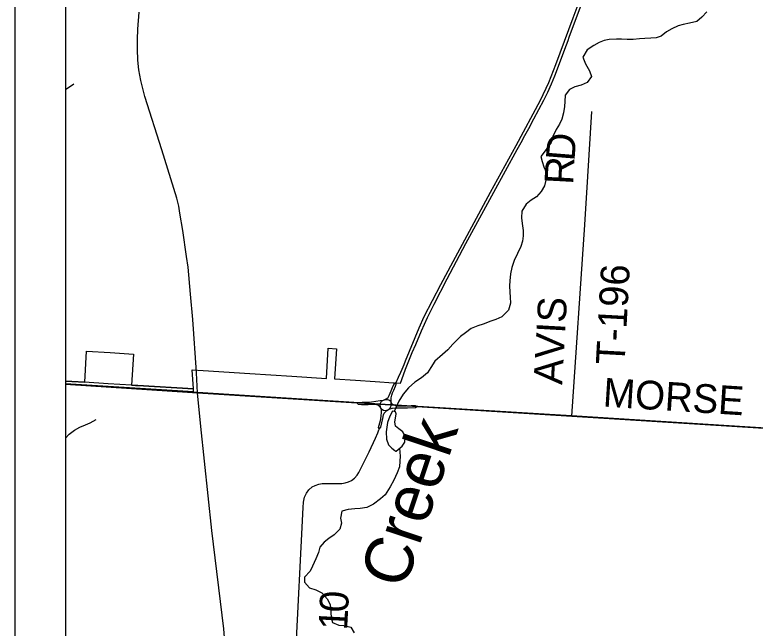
# Model space of a CAD drawing. Extents: x 0 to 91.3, y -0.7 to 22.
# Drawn here: x 2 to 3.464, y 15.231 to 16.443 of the extents above; entities that cross this region are included whole.
import ezdxf

# ---------------------------------------------------------------- set-up
doc = ezdxf.new("R2010")
doc.units = 0
for name, color, linetype in [('GM_X_City_Street', 7, 'Continuous'), ('GM_X_Corporation', 7, 'Continuous'), ('GM_X_County_Road', 7, 'Continuous'), ('GM_X_County_Road_Text', 7, 'Continuous'), ('GM_X_Minor_Lake', 7, 'Continuous'), ('GM_X_Minor_River', 7, 'Continuous'), ('GM_X_Minor_River_Text', 7, 'Continuous'), ('GM_X_Township_Road', 7, 'Continuous'), ('GM_X_Township_Road_Text', 7, 'Continuous'), ('SH_Data', 7, 'Continuous')]:
    doc.layers.add(name, color=color, linetype=linetype)

msp = doc.modelspace()

# ---------------------------------------------------------------- linework, layer by layer
at = {"layer": 'GM_X_City_Street'}
msp.add_line((2.1164, 16.3065), (2.1, 16.2954), dxfattribs=at)
at = {"layer": 'GM_X_Corporation'}
for points in [[(2.1, 20.8844), (2.1, 14.1), (4.5273, 14.1), (4.5361, 14.2234), (4.5616, 14.5843), (4.5901, 15.0403), (4.6027, 15.2253), (4.6241, 15.5494), (4.624, 15.5538), (4.6966, 16.7952), (4.7039, 16.921), (4.7369, 17.4842), (4.7381, 17.5094), (4.7391, 17.5254), (4.7562, 17.8002), (4.7688, 17.9561), (4.7799, 18.0944), (4.7833, 18.1361), (4.8242, 18.6326)], [(2.1, 20.8844), (2.1, 15.7138), (2.3611, 15.6969), (2.7426, 15.6727), (3.1007, 15.6507), (3.7652, 15.6088), (4.1118, 15.5861), (4.6241, 15.5494), (4.624, 15.5538), (4.6966, 16.7952), (4.7039, 16.921), (4.7369, 17.4842), (4.7381, 17.5094), (4.7391, 17.5254), (4.7562, 17.8002), (4.7688, 17.9561), (4.7799, 18.0944), (4.7833, 18.1361), (4.8242, 18.6326)], [(2.1, 19.7378), (2.1, 15.7194), (2.1381, 15.7171), (2.1418, 15.7788), (2.1882, 15.7758), (2.2344, 15.7729), (2.2307, 15.7114), (2.2386, 15.7109), (2.2429, 15.7106), (2.3529, 15.7042), (2.3503, 15.7415), (2.3722, 15.7401), (2.4649, 15.7342), (2.5474, 15.729), (2.6159, 15.7246), (2.6196, 15.7843), (2.6356, 15.7834), (2.6317, 15.7236), (2.6736, 15.721), (2.7121, 15.7185), (2.7484, 15.7162), (2.7508, 15.7161), (2.7626, 15.7153), (2.7651, 15.7226), (2.772, 15.7427), (2.7787, 15.7592), (2.7857, 15.7757), (2.7929, 15.792), (2.8036, 15.819), (2.8156, 15.8454), (2.8288, 15.8713), (2.8547, 15.9217), (2.8915, 15.9917), (2.9467, 16.093), (2.9928, 16.1772), (3.0007, 16.191), (3.0085, 16.2049), (3.0162, 16.219), (3.0262, 16.2376), (3.0361, 16.2562), (3.046, 16.2749), (3.0536, 16.2907), (3.0608, 16.3068), (3.0675, 16.3231), (3.0905, 16.3839), (3.0938, 16.3928), (3.0961, 16.399), (3.1204, 16.4646)]]:
    msp.add_lwpolyline(points, dxfattribs=at)
for points in [[(2.1, 15.7194), (2.1, 15.7146), (2.3533, 15.6987), (2.3529, 15.7044), (2.2429, 15.7106), (2.2386, 15.7109), (2.2307, 15.7114), (2.1844, 15.7142), (2.138, 15.7171)], [(2.1, 15.7138), (2.1, 14.1), (4.5273, 14.1), (4.5361, 14.2234), (4.5616, 14.5843), (4.5901, 15.0403), (4.6027, 15.2253), (4.6241, 15.5494), (4.1118, 15.5861), (3.7652, 15.6088), (3.1007, 15.6507), (2.7426, 15.6727), (2.3611, 15.6969)]]:
    msp.add_lwpolyline(points, close=True, dxfattribs=at)
at = {"layer": 'GM_X_County_Road'}
for p, q in [((2.3614, 15.6963), (2.3591, 15.7358)), ((2.1, 15.7132), (2.3511, 15.697)), ((2.3511, 15.697), (2.3614, 15.6963)), ((2.3614, 15.6963), (2.676, 15.6764))]:
    msp.add_line(p, q, dxfattribs=at)
for points in [[(2.7694, 15.7521), (2.7721, 15.7592), (2.7994, 15.825), (2.8095, 15.8468), (2.8423, 15.9103), (2.8668, 15.9561), (2.94, 16.0927), (2.9908, 16.1849), (3.0391, 16.2749), (3.0556, 16.3094), (3.0694, 16.3453), (3.1035, 16.4374), (3.1154, 16.469)], [(2.3591, 15.7358), (2.3591, 15.7368), (2.3519, 15.8412), (2.3474, 15.8915), (2.3425, 15.9446), (2.3397, 15.9659), (2.3323, 16.0171), (2.3265, 16.0511), (2.3242, 16.0649), (2.3205, 16.0812), (2.2904, 16.1763), (2.2571, 16.2817), (2.2491, 16.3133), (2.2452, 16.3346), (2.2433, 16.3535), (2.2424, 16.3754), (2.2427, 16.3943), (2.2435, 16.415), (2.2455, 16.4488)], [(2.7537, 15.7167), (2.7586, 15.7273), (2.7631, 15.737), (2.7657, 15.743), (2.7694, 15.7521)], [(2.7288, 15.6819), (2.7343, 15.6841), (2.7383, 15.6871), (2.7402, 15.6912), (2.7437, 15.7001), (2.748, 15.7099), (2.7505, 15.7148), (2.7537, 15.7167)], [(2.744, 15.6761), (2.7438, 15.6804), (2.7441, 15.686), (2.7452, 15.6918), (2.7465, 15.6963), (2.7489, 15.7018), (2.7522, 15.7091), (2.754, 15.7132), (2.7537, 15.7167)], [(2.4217, 15.1187), (2.413, 15.2298), (2.3896, 15.4238), (2.3677, 15.6299), (2.3614, 15.6963)], [(2.676, 15.6764), (2.6788, 15.6772), (2.6868, 15.6777), (2.6949, 15.6779), (2.7049, 15.6786), (2.7137, 15.6795), (2.722, 15.6808), (2.7288, 15.6819), (2.7307, 15.6825), (2.7341, 15.6831), (2.7368, 15.6828), (2.7391, 15.6822), (2.7413, 15.6813), (2.7433, 15.679), (2.744, 15.6761), (2.7468, 15.6737), (2.7526, 15.6709), (2.7561, 15.6704), (2.7617, 15.6706), (2.7735, 15.6708), (2.7833, 15.6709), (2.7914, 15.6709), (2.7944, 15.669)], [(2.676, 15.6764), (2.6788, 15.6738), (2.685, 15.6731), (2.6926, 15.673), (2.6986, 15.6733), (2.7061, 15.6736), (2.7115, 15.6736), (2.7149, 15.6732), (2.718, 15.6717), (2.7208, 15.6692), (2.7231, 15.6666)], [(2.7231, 15.6666), (2.7226, 15.6691), (2.7221, 15.6717), (2.7224, 15.6746), (2.7233, 15.6772), (2.725, 15.6798), (2.7288, 15.6819)], [(2.7435, 15.6686), (2.7442, 15.671), (2.744, 15.6761)], [(2.7203, 15.6245), (2.7191, 15.6278), (2.7217, 15.6369), (2.7234, 15.6439), (2.7244, 15.6512), (2.7248, 15.657), (2.7246, 15.6628), (2.7231, 15.6666)], [(2.7203, 15.6245), (2.7233, 15.6281), (2.7257, 15.637), (2.7278, 15.6454), (2.7289, 15.6524), (2.7301, 15.6559), (2.7332, 15.6596), (2.7355, 15.6616), (2.7387, 15.6635)], [(2.7231, 15.6666), (2.7254, 15.6642), (2.7289, 15.6621), (2.7326, 15.6615), (2.7354, 15.662), (2.7387, 15.6635)], [(2.7387, 15.6635), (2.742, 15.6649), (2.7465, 15.6662), (2.7525, 15.6664), (2.7639, 15.6666), (2.7764, 15.6668), (2.7921, 15.6672), (2.7944, 15.669)], [(2.7387, 15.6635), (2.7413, 15.6653), (2.7433, 15.6678), (2.7435, 15.6686)], [(2.7944, 15.669), (3.1009, 15.6502), (3.7654, 15.6083), (4.112, 15.5855)], [(2.7132, 15.6069), (2.7177, 15.6174), (2.7196, 15.6231), (2.7203, 15.6245)], [(2.5547, 15.1688), (2.5697, 15.4694), (2.5705, 15.4803), (2.5728, 15.4899), (2.5763, 15.4977), (2.5812, 15.5047), (2.5876, 15.5101), (2.5937, 15.5132), (2.6007, 15.5156), (2.6073, 15.5169), (2.616, 15.5171), (2.6392, 15.5169), (2.6465, 15.5171), (2.6527, 15.5182), (2.6594, 15.5201), (2.6656, 15.5229), (2.6715, 15.5277), (2.6768, 15.5334), (2.6799, 15.5387), (2.6835, 15.5451), (2.7003, 15.5799), (2.7132, 15.6069)]]:
    msp.add_lwpolyline(points, dxfattribs=at)
at = {"layer": 'GM_X_Minor_Lake'}
for points in [[(2.7654, 15.5909), (2.7712, 15.5984), (2.7716, 15.6087), (2.7671, 15.6193), (2.7592, 15.6251), (2.7528, 15.6304), (2.7509, 15.6388), (2.7525, 15.6464), (2.7537, 15.6547), (2.7522, 15.6589), (2.7469, 15.6601), (2.7415, 15.6502), (2.7369, 15.6373), (2.7341, 15.6191), (2.7344, 15.6043), (2.7389, 15.5937), (2.7453, 15.5868), (2.7509, 15.5822)], [(2.7509, 15.5822), (2.7533, 15.5812), (2.7539, 15.5812), (2.7654, 15.5909)]]:
    msp.add_lwpolyline(points, dxfattribs=at)
at = {"layer": 'GM_X_Minor_River'}
for points in [[(3.3678, 16.4496), (3.3579, 16.4387), (3.3479, 16.4304), (3.3335, 16.4267), (3.3213, 16.4245), (3.3111, 16.4215), (3.2989, 16.4159), (3.2879, 16.4095), (3.2776, 16.4012), (3.2677, 16.3982), (3.2574, 16.3975), (3.2456, 16.3968), (3.2346, 16.3961), (3.2221, 16.3947), (3.2103, 16.3948), (3.199, 16.3956), (3.1891, 16.3953), (3.1747, 16.3946), (3.1648, 16.3924), (3.1549, 16.389), (3.1446, 16.3826), (3.1316, 16.374), (3.1228, 16.36), (3.1284, 16.3467), (3.1363, 16.333), (3.14, 16.3212), (3.1316, 16.3095), (3.1198, 16.3046), (3.1069, 16.3009), (3.0962, 16.2956), (3.0878, 16.2843)], [(3.0878, 16.2843), (3.0874, 16.2718), (3.0869, 16.2619), (3.0846, 16.2494), (3.0811, 16.2369), (3.0768, 16.227), (3.0703, 16.2164), (3.0634, 16.2028), (3.0599, 16.1911), (3.0522, 16.1797), (3.0396, 16.1635), (3.0422, 16.1536), (3.0459, 16.143), (3.0504, 16.1323), (3.0511, 16.1217), (3.0472, 16.1054), (3.0403, 16.094), (3.0311, 16.0838), (3.0205, 16.0771), (3.0106, 16.0692), (3.0021, 16.0552), (3.0017, 16.0423), (3.0027, 16.0312), (3.0049, 16.0168), (3.0049, 16.0066), (3.0037, 15.9959), (3.0002, 15.9853), (2.9936, 15.9717), (2.9871, 15.9577), (2.9828, 15.9437), (2.9801, 15.9312), (2.9785, 15.9179), (2.9781, 15.908), (2.9787, 15.8951), (2.9794, 15.8853), (2.9797, 15.8735), (2.9762, 15.8598), (2.9625, 15.8466), (2.9507, 15.841), (2.9412, 15.838), (2.926, 15.8321), (2.9153, 15.8287), (2.9024, 15.8235), (2.8909, 15.8148), (2.881, 15.8077), (2.8661, 15.7926), (2.8562, 15.7812), (2.8455, 15.7718), (2.8302, 15.759), (2.8226, 15.7461), (2.8157, 15.7359), (2.8042, 15.7258), (2.7909, 15.7171), (2.7783, 15.7062), (2.768, 15.6937), (2.7588, 15.6797), (2.7499, 15.6594)], [(2.1, 15.6068), (2.1075, 15.6142), (2.1178, 15.6225), (2.1284, 15.6281), (2.1395, 15.633), (2.149, 15.6371), (2.1608, 15.6435)], [(2.7607, 15.5869), (2.7619, 15.5708), (2.7614, 15.5609), (2.7602, 15.5499), (2.756, 15.5378), (2.7494, 15.5238), (2.7421, 15.5102), (2.7322, 15.4947), (2.7226, 15.4868), (2.7089, 15.4762), (2.696, 15.4695), (2.683, 15.4673), (2.672, 15.4666), (2.6591, 15.4655), (2.6462, 15.4622), (2.6438, 15.4485), (2.6461, 15.4383), (2.6426, 15.4265), (2.6315, 15.4152), (2.6208, 15.408), (2.6113, 15.4013), (2.6029, 15.3911), (2.6005, 15.3808), (2.5951, 15.368), (2.5886, 15.3536), (2.584, 15.3437), (2.5729, 15.332), (2.5728, 15.3218), (2.5826, 15.3107), (2.5951, 15.3069), (2.6069, 15.3011), (2.6174, 15.2893), (2.6234, 15.2775), (2.6248, 15.2627), (2.6251, 15.2516), (2.6277, 15.2421), (2.6402, 15.2368), (2.6501, 15.2363), (2.6645, 15.2332), (2.6705, 15.2218)]]:
    msp.add_lwpolyline(points, dxfattribs=at)
at = {"layer": 'GM_X_Township_Road'}
msp.add_line((3.1325, 16.1241), (3.1403, 16.2523), dxfattribs=at)
msp.add_lwpolyline([(3.1009, 15.6502), (3.1268, 16.0284), (3.1325, 16.1241)], dxfattribs=at)
at = {"layer": 'SH_Data'}
for p, q in [((2, 21), (2, 14)), ((2.1, 20.9), (2.1, 14.1))]:
    msp.add_line(p, q, dxfattribs=at)

# ---------------------------------------------------------------- texts
at = {"layer": 'GM_X_County_Road_Text'}
for s, height, rotation, p in [('MORSE', 0.05682, 356.3984, (3.1615, 15.6692)), ('0', 0.0568, 87.0871, (2.6586, 15.2612)), ('1', 0.0568, 87.0466, (2.6568, 15.2262))]:
    msp.add_text(s, height=height, rotation=rotation, dxfattribs=at).set_placement(p)
at = {"layer": 'GM_X_Minor_River_Text'}
msp.add_text('Creek', height=0.0947, rotation=71.5253, dxfattribs=at).set_placement((2.7703, 15.3054))
at = {"layer": 'GM_X_Township_Road_Text'}
for s, height, rotation, p in [('D', 0.0568, 85.4197, (3.1061, 16.1531)), ('R', 0.0568, 86.8877, (3.1035, 16.1069)), ('T-196', 0.05682, 86.9141, (3.2052, 15.7507)), ('AVIS', 0.05682, 86.7543, (3.0819, 15.7115))]:
    msp.add_text(s, height=height, rotation=rotation, dxfattribs=at).set_placement(p)

doc.saveas('drawing.dxf')
